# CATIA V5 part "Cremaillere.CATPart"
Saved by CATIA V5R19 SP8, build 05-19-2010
Part number: 552201
Nomenclature: 552201
Source: Unknown
Description: PART-552201-DESC
Bounding box of the stored display mesh (mm): x -176 to -104, y 0 to 15, z -4 to 4
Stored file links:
  D:\Documents\1_Travail\1 - ac-limoges.fr\ac-limoges.fr\Emmanuel Maynard - STI2D_Turgot\1 - IT-I2D\Activités_IT_Première\IT_3_Abris_bus\Maquettes numériques\Abribus_eleve\Cremaillere.CATPart
  D:\Documents\1_Travail\1 - ac-limoges.fr\ac-limoges.fr\Emmanuel Maynard - STI2D_Turgot\1 - IT-I2D\Activités_IT_Première\IT_3_Abris_bus\Maquettes numériques\Abribus\0-Abribus.CATProduct
  D:\Documents\1_Travail\1 - ac-limoges.fr\ac-limoges.fr\Emmanuel Maynard - STI2D_Turgot\1 - IT-I2D\Activités_IT_Première\IT_3_Abris_bus\Maquettes numériques\Abribus\Slide_Beam_0824-192.CATPart
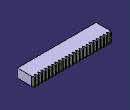
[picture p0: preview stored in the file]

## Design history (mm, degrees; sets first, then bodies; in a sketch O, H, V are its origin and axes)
AxisSystem1: origin (0, 0, 0), X (1, 0, 0), Y (0, 1, 0), Z (0, 0, 1)
Set1
  DatumSurface1
Set2
  Sketch1 on YZ plane of AxisSystem1, origin (0, 0, 0), H (0, 1, 0), V (0, 0, 1)
    point P1 (7.3163, 0)
    line L1 (20.8819, 4) -> (20.8819, -4)
    line L2 (20.8819, -4) -> (-6.2492, -4)
    line L3 (-6.2492, -4) -> (-6.2492, 4)
    line L4 (-6.2492, 4) -> (20.8819, 4)
    length L3 = 8
    coincidence: P1 H
    vertical: L1 V, L3 V
    horizontal: L2 H, L4 H
    equidistance: L1 L3 P1, L2 L4 P1
Body1 "552201" (main body)
  Solid1: solid without history
  Pocket1: profile Sketch1, direction (-1, 0, 0), through (limit type 3), opposite side through (limit type 3), outer side
  Plane1: type Offset, RefPlane face of Solid1, Offset 72
  Split1: SplitPlane Plane1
